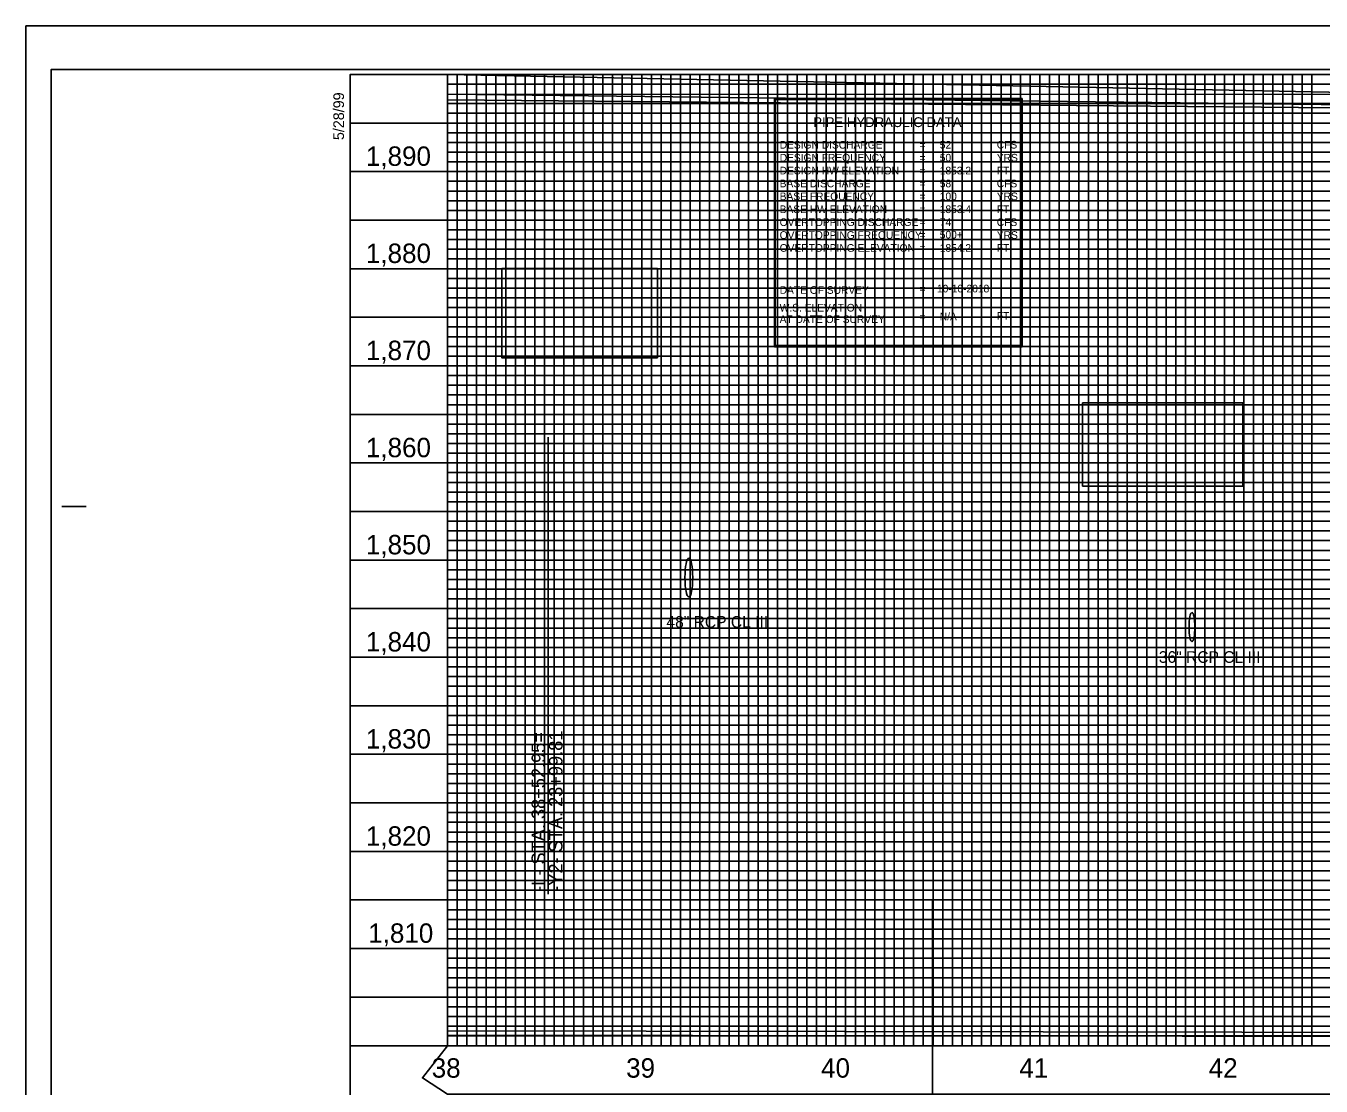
# Model space of a CAD drawing. Extents: x 557032 to 562069, y 513430 to 515874.
# Drawn here: x 557032 to 557699, y 515328 to 515874 of the extents above; entities that cross this region are included whole.
import ezdxf

# ---------------------------------------------------------------- set-up
doc = ezdxf.new("R2010")
doc.units = 0
for name, color, linetype in [('Default', 7, 'Continuous'), ('Exist Profile Cell', 7, 'Continuous'), ('Exist Vertical Profile Horizontal Axis Label Major', 7, 'Continuous'), ('Exist Vertical Profile Vertical Axis Label', 7, 'Continuous'), ('Prop Vertical Profile Curve Label', 7, 'Continuous'), ('Prop VPI Label', 7, 'Continuous'), ('Scratch_Level_1', 7, 'Continuous'), ('Scratch_Level_5', 7, 'Continuous'), ('Sheet Cutting Line CELL', 7, 'Continuous'), ('Sheet DOT Grid CELL', 7, 'Continuous'), ('Sheet Layout Profile Border Port 1', 7, 'Continuous'), ('Sheet Plot Border Inside CELL', 7, 'Continuous'), ('Sheet Plot Border Outside CELL', 7, 'Continuous'), ('Sheet Profile CELL', 7, 'Continuous'), ('Sheet Profile Grid Major CELL', 7, 'Continuous'), ('Sheet Profile Grid Middle CELL', 7, 'Continuous'), ('Sheet Profile Grid Minor CELL', 7, 'Continuous')]:
    doc.layers.add(name, color=color, linetype=linetype)

msp = doc.modelspace()

# ---------------------------------------------------------------- linework, layer by layer
at = {"layer": 'Default'}
for centre, major_axis in [((557373.73, 515590.31), (0, 10)), ((557632.73, 515564.81), (0, 7.5))]:
    msp.add_ellipse(centre, major_axis=major_axis, ratio=0.2, dxfattribs=at)
at = {"layer": 'Exist Profile Cell'}
msp.add_line((557499.18, 515173.85), (557499.18, 515423.85), dxfattribs=at)
at = {"layer": 'Prop Vertical Profile Curve Label'}
for points in [[(557417.87, 515836.9), (557545.27, 515836.9), (557545.27, 515709.09), (557417.87, 515709.09)], [(557277.44, 515749.39), (557357.56, 515749.39), (557357.56, 515703.4), (557277.44, 515703.4)], [(557576.47, 515680.15), (557658.85, 515680.15), (557658.85, 515637.38), (557576.47, 515637.38)]]:
    msp.add_lwpolyline(points, close=True, dxfattribs=at)
at = {"layer": 'Prop VPI Label'}
msp.add_line((557301.28, 515662.58), (557301.28, 515427.35), dxfattribs=at)
msp.add_lwpolyline([(557418.13, 515709.83), (557544.69, 515709.83), (557544.69, 515836.39), (557418.13, 515836.39)], close=True, dxfattribs=at)
at = {"layer": 'Scratch_Level_1'}
for p in [(557649.45, 515354.16), (557649.45, 515354.16), (557649.45, 515353.5)]:
    msp.add_line(p, (557649.45, 515680.98), dxfattribs=at)
at = {"layer": 'Scratch_Level_5'}
for p, q in [((557249.42, 515839.17), (557249.42, 515356.85)), ((557249.45, 515836.19), (557249.45, 515354.68))]:
    msp.add_line(p, q, dxfattribs=at)
msp.add_lwpolyline([(558499.4, 515824.23), (557249.45, 515849.28), (557249.45, 515349.28), (557236.61, 515332.67), (557249.45, 515324.28), (558649.45, 515324.28), (558662.72, 515334.01), (558649.45, 515349.28), (558649.45, 515688.23), (558499.4, 515688.23)], close=True, dxfattribs=at)
for points in [[(558649.42, 515686.42), (558641.97, 515686.42), (558497.02, 515687.96), (558497.02, 515823.15), (558090.9, 515829.21), (557249.42, 515839.17)], [(558649.45, 515682.57), (558492.81, 515683.83), (558490.11, 515820.17), (558049.46, 515829.04), (557249.45, 515836.19)], [(557249.42, 515356.85), (558373.93, 515355.08), (558412.39, 515354.77), (558649.42, 515355.8)], [(557249.45, 515354.68), (558384.27, 515353.2), (558399.94, 515350.88), (558440.57, 515354.03), (558649.45, 515354.48)]]:
    msp.add_lwpolyline(points, dxfattribs=at)
at = {"layer": 'Sheet Cutting Line CELL'}
for p, q in [((558716.45, 515874.28), (557032.45, 515874.28)), ((557032.45, 515874.28), (557032.45, 514774.28))]:
    msp.add_line(p, q, dxfattribs=at)
at = {"layer": 'Sheet DOT Grid CELL'}
for p, q in [((557249.45, 515349.28), (557249.45, 515849.28)), ((557299.45, 515349.28), (557299.45, 515849.28)), ((557349.45, 515349.28), (557349.45, 515849.28)), ((557399.45, 515349.28), (557399.45, 515849.28)), ((557449.45, 515349.28), (557449.45, 515849.28)), ((557499.45, 515349.28), (557499.45, 515849.28)), ((557549.45, 515349.28), (557549.45, 515849.28)), ((557599.45, 515349.28), (557599.45, 515849.28)), ((557649.45, 515349.28), (557649.45, 515849.28)), ((558499.4, 515799.28), (557199.45, 515799.28)), ((558499.4, 515749.28), (557199.45, 515749.28)), ((558499.45, 515699.28), (557199.45, 515699.28)), ((558699.45, 515649.28), (557199.45, 515649.28)), ((558699.45, 515599.28), (557199.45, 515599.28)), ((558699.45, 515549.28), (557199.45, 515549.28)), ((558699.45, 515499.28), (557199.45, 515499.28)), ((558699.45, 515449.28), (557199.45, 515449.28)), ((558699.45, 515399.28), (557199.45, 515399.28))]:
    msp.add_line(p, q, dxfattribs=at)
at = {"layer": 'Sheet Layout Profile Border Port 1'}
for points in [[(557249.45, 515688.23), (557249.45, 515349.28), (558649.45, 515349.28), (558649.45, 515688.23)], [(557249.45, 515688.23), (557249.45, 515354.68)], [(557249.45, 515688.23), (557249.45, 515354.13)]]:
    msp.add_lwpolyline(points, dxfattribs=at)
at = {"layer": 'Sheet Plot Border Inside CELL'}
msp.add_lwpolyline([(557045.45, 514796.73), (558711.95, 514796.73), (558711.95, 515851.83), (557045.45, 515851.83)], close=True, dxfattribs=at)
at = {"layer": 'Sheet Plot Border Outside CELL'}
msp.add_lwpolyline([(557032.45, 514774.28), (558716.45, 514774.28), (558716.45, 515874.28), (557032.45, 515874.28)], close=True, dxfattribs=at)
at = {"layer": 'Sheet Profile CELL'}
for p, q in [((557050.95, 515626.78), (557063.45, 515626.78)), ((557199.45, 515349.28), (558699.45, 515349.28))]:
    msp.add_line(p, q, dxfattribs=at)
msp.add_lwpolyline([(558699.45, 515849.28), (557199.45, 515849.28), (557199.45, 514799.28), (558699.45, 514799.28)], close=True, dxfattribs=at)
at = {"layer": 'Sheet Profile Grid Major CELL'}
for points in [[(557249.45, 515849.28), (557249.45, 515349.28), (557299.45, 515349.28), (557299.45, 515849.28), (557349.45, 515849.28), (557349.45, 515349.28), (557399.45, 515349.28), (557399.45, 515849.28), (557449.45, 515849.28), (557449.45, 515349.28), (557499.45, 515349.28), (557499.45, 515849.28), (557549.45, 515849.28), (557549.45, 515349.28), (557599.45, 515349.28), (557599.45, 515849.28), (557649.45, 515849.28), (557649.45, 515349.28), (557699.45, 515349.28)], [(557199.45, 515799.28), (558499.45, 515799.28)], [(558499.45, 515749.28), (557199.45, 515749.28), (557199.45, 515699.28), (558499.45, 515699.28)], [(558699.45, 515649.28), (557199.45, 515649.28), (557199.45, 515599.28), (558699.45, 515599.28)], [(558699.45, 515549.28), (557199.45, 515549.28), (557199.45, 515499.28), (558699.45, 515499.28)], [(558699.45, 515449.28), (557199.45, 515449.28), (557199.45, 515449.28), (557199.45, 515399.28), (558699.45, 515399.28)]]:
    msp.add_lwpolyline(points, dxfattribs=at)
at = {"layer": 'Sheet Profile Grid Middle CELL'}
msp.add_line((557199.45, 515824.28), (558499.4, 515824.28), dxfattribs=at)
for points in [[(557274.45, 515849.28), (557274.45, 515349.28), (557324.45, 515349.28), (557324.45, 515849.28), (557374.45, 515849.28), (557374.45, 515349.28), (557424.45, 515349.28), (557424.45, 515849.28), (557474.45, 515849.28), (557474.45, 515349.28), (557524.45, 515349.28), (557524.45, 515849.28), (557574.45, 515849.28), (557574.45, 515349.28), (557624.45, 515349.28), (557624.45, 515849.28), (557674.45, 515849.28), (557674.45, 515349.28), (557724.45, 515349.28)], [(558499.45, 515774.28), (557199.45, 515774.28), (557199.45, 515724.28), (558499.45, 515724.28)], [(558699.45, 515674.28), (557199.45, 515674.28), (557199.45, 515624.28), (558524.45, 515624.28)], [(558699.45, 515574.28), (557199.45, 515574.28), (557199.45, 515524.28), (558699.45, 515524.28)], [(558699.45, 515474.28), (557199.45, 515474.28), (557199.45, 515424.28), (558699.45, 515424.28)], [(558699.45, 515374.28), (557199.45, 515374.28)]]:
    msp.add_lwpolyline(points, dxfattribs=at)
at = {"layer": 'Sheet Profile Grid Minor CELL'}
for p, q in [((557249.45, 515844.28), (558499.45, 515844.28)), ((557249.45, 515839.28), (557249.45, 515839.28)), ((558499.45, 515839.28), (557249.45, 515838.93)), ((557249.45, 515834.28), (558499.45, 515834.28)), ((558499.4, 515714.28), (557249.45, 515714.28)), ((558499.45, 515709.28), (557249.45, 515709.28)), ((558499.45, 515704.28), (557249.45, 515704.28)), ((557249.45, 515694.28), (558499.45, 515694.28)), ((558499.45, 515689.28), (557249.45, 515689.28)), ((557249.45, 515684.28), (558649.45, 515684.28)), ((558649.45, 515664.28), (557249.45, 515664.28)), ((557249.45, 515659.28), (558649.45, 515659.28)), ((558649.45, 515639.28), (557249.45, 515639.28)), ((557249.45, 515634.28), (558649.45, 515634.28)), ((558649.45, 515614.28), (557249.45, 515614.28)), ((557249.45, 515609.28), (558649.45, 515609.28)), ((558649.45, 515604.28), (557249.45, 515604.28)), ((557249.45, 515594.28), (558649.45, 515594.28)), ((558649.45, 515589.28), (557249.45, 515589.28)), ((557249.45, 515584.28), (558649.45, 515584.28)), ((558649.45, 515579.28), (557249.45, 515579.28)), ((557249.45, 515569.28), (558649.45, 515569.28)), ((558649.45, 515564.28), (557249.45, 515564.28)), ((557249.45, 515559.28), (558649.45, 515559.28)), ((558649.45, 515554.28), (557249.45, 515554.28)), ((557249.45, 515544.28), (558649.45, 515544.28)), ((558649.45, 515539.28), (557249.45, 515539.28)), ((557249.45, 515534.28), (558649.45, 515534.28)), ((558649.45, 515529.28), (557249.45, 515529.28)), ((557249.45, 515519.28), (558649.45, 515519.28)), ((558649.45, 515514.28), (557249.45, 515514.28)), ((557249.45, 515509.28), (558649.45, 515509.28)), ((558649.45, 515504.28), (557249.45, 515504.28)), ((557249.45, 515494.28), (558649.45, 515494.28)), ((558649.45, 515489.28), (557249.45, 515489.28)), ((557249.45, 515484.28), (558649.45, 515484.28)), ((558649.45, 515479.28), (557249.45, 515479.28)), ((557249.45, 515469.28), (558649.45, 515469.28)), ((558649.45, 515464.28), (557249.45, 515464.28)), ((558649.45, 515459.28), (557249.45, 515459.28)), ((558649.45, 515454.28), (557249.45, 515454.28)), ((557249.45, 515444.28), (558649.45, 515444.28)), ((558649.45, 515439.28), (557249.45, 515439.28)), ((557249.45, 515434.28), (558649.45, 515434.28)), ((558649.45, 515429.28), (557249.45, 515429.28)), ((557249.45, 515419.28), (558649.45, 515419.28)), ((558649.45, 515414.28), (557249.45, 515414.28)), ((557249.45, 515409.28), (558649.45, 515409.28)), ((558649.45, 515404.28), (557249.45, 515404.28)), ((557249.45, 515394.28), (558649.45, 515394.28)), ((558649.45, 515389.28), (557249.45, 515389.28)), ((557249.45, 515384.28), (558649.45, 515384.28)), ((558649.45, 515379.28), (557249.45, 515379.28)), ((557249.45, 515369.28), (558649.45, 515369.28)), ((558649.45, 515364.28), (557249.45, 515364.28)), ((557249.45, 515359.28), (558649.45, 515359.28))]:
    msp.add_line(p, q, dxfattribs=at)
for points in [[(557254.45, 515849.28), (557254.45, 515349.28), (557259.45, 515349.28), (557259.45, 515849.28), (557264.45, 515849.28), (557264.45, 515349.28), (557269.45, 515349.28), (557269.45, 515849.28), (557279.45, 515849.28), (557279.45, 515349.28), (557284.45, 515349.28), (557284.45, 515849.28), (557289.45, 515849.28), (557289.45, 515349.28), (557294.45, 515349.28), (557304.45, 515349.28), (557309.45, 515349.28), (557309.45, 515849.28), (557314.45, 515849.28), (557314.45, 515349.28), (557319.45, 515349.28), (557319.45, 515849.28), (557329.45, 515849.28), (557329.45, 515349.28), (557334.45, 515349.28), (557334.45, 515849.28), (557339.45, 515849.28), (557339.45, 515349.28), (557344.45, 515349.28), (557344.45, 515849.28), (557354.45, 515849.28), (557354.45, 515349.28), (557359.45, 515349.28), (557359.45, 515849.28), (557364.45, 515849.28), (557364.45, 515349.28), (557369.45, 515349.28), (557369.45, 515849.28), (557379.45, 515849.28), (557379.45, 515349.28), (557384.45, 515349.28), (557384.45, 515849.28), (557389.45, 515849.28), (557389.45, 515349.28), (557394.45, 515349.28), (557394.45, 515849.28), (557404.45, 515849.28), (557404.45, 515349.28), (557409.45, 515349.28), (557409.45, 515849.28), (557414.45, 515849.28), (557414.45, 515349.28), (557419.45, 515349.28), (557419.45, 515849.28), (557429.45, 515849.28), (557429.45, 515349.28), (557434.45, 515349.28), (557434.45, 515849.28), (557439.45, 515849.28), (557439.45, 515349.28), (557444.45, 515349.28), (557444.45, 515849.28), (557454.45, 515849.28), (557454.45, 515349.28), (557459.45, 515349.28), (557459.45, 515849.28), (557464.45, 515849.28), (557464.45, 515349.28)], [(557294.45, 515349.28), (557294.45, 515849.28), (557304.45, 515849.28), (557304.45, 515349.28)], [(557464.45, 515349.28), (557469.45, 515349.28), (557469.45, 515849.28), (557479.45, 515849.28), (557479.45, 515349.28), (557484.45, 515349.28), (557484.45, 515849.28), (557489.45, 515849.28), (557489.45, 515349.28), (557494.45, 515349.28), (557494.45, 515849.28), (557504.45, 515849.28), (557504.45, 515349.28), (557509.45, 515349.28), (557509.45, 515849.28), (557514.45, 515849.28), (557514.45, 515349.28), (557519.45, 515349.28), (557519.45, 515849.28), (557529.45, 515849.28), (557529.45, 515349.28), (557534.45, 515349.28), (557534.45, 515849.28), (557539.45, 515849.28), (557539.45, 515349.28), (557544.45, 515349.28), (557544.45, 515849.28), (557554.45, 515849.28), (557554.45, 515349.28), (557559.45, 515349.28), (557559.45, 515849.28), (557564.45, 515849.28), (557564.45, 515349.28), (557569.45, 515349.28), (557569.45, 515849.28), (557579.45, 515849.28), (557579.45, 515349.28), (557584.45, 515349.28), (557584.45, 515849.28), (557589.45, 515849.28), (557589.45, 515349.28), (557594.45, 515349.28), (557594.45, 515849.28), (557604.45, 515849.28), (557604.45, 515349.28), (557609.45, 515349.28), (557609.45, 515849.28), (557614.45, 515849.28), (557614.45, 515349.28), (557619.45, 515349.28), (557619.45, 515849.28), (557629.45, 515849.28), (557629.45, 515349.28), (557634.45, 515349.28), (557634.45, 515849.28), (557639.45, 515849.28), (557639.45, 515349.28), (557644.45, 515349.28), (557644.45, 515849.28), (557654.45, 515849.28), (557654.45, 515349.28), (557659.45, 515349.28), (557659.45, 515849.28), (557664.45, 515849.28), (557664.45, 515349.28), (557669.45, 515349.28), (557669.45, 515849.28), (557679.45, 515849.28), (557679.45, 515349.28), (557684.45, 515349.28), (557684.45, 515849.28), (557689.45, 515849.28), (557689.45, 515349.28), (557694.45, 515349.28), (557694.45, 515849.28), (557704.45, 515849.28)], [(558499.45, 515829.28), (557249.45, 515829.28), (557249.45, 515819.28), (558499.45, 515819.28)], [(558499.4, 515814.28), (557249.45, 515814.28), (557249.45, 515809.28), (558499.45, 515809.28)], [(558499.45, 515804.28), (557249.45, 515804.28), (557249.45, 515794.28), (558499.45, 515794.28)], [(558499.45, 515789.28), (557249.45, 515789.28), (557249.45, 515784.28), (558499.45, 515784.28)], [(558499.45, 515779.28), (557249.45, 515779.28), (557249.45, 515769.28), (558499.45, 515769.28)], [(558499.45, 515764.28), (557249.45, 515764.28), (557249.45, 515759.28), (558499.45, 515759.28)], [(558499.45, 515754.28), (557249.45, 515754.28), (557249.45, 515744.28), (558499.45, 515744.28)], [(558499.45, 515739.18), (557249.55, 515739.18), (557249.55, 515734.28), (558499.45, 515734.28)], [(558499.45, 515729.28), (557249.45, 515729.28), (557249.45, 515719.28), (558499.45, 515719.28)], [(558649.45, 515679.28), (557249.45, 515679.28), (557249.45, 515669.28), (558649.45, 515669.28)], [(558649.45, 515654.28), (557249.45, 515654.28), (557249.45, 515644.28), (558649.45, 515644.28)], [(558649.45, 515629.28), (557249.45, 515629.28), (557249.45, 515619.28), (558649.45, 515619.28)], [(558649.45, 515354.28), (557249.45, 515354.28)]]:
    msp.add_lwpolyline(points, dxfattribs=at)

# ---------------------------------------------------------------- texts
at = {"layer": 'Default'}
for s, p in [('48" RCP CL III', (557362.21, 515564.46)), ('36" RCP CL III', (557615.69, 515546.37))]:
    msp.add_text(s, height=6, dxfattribs=at).set_placement(p)
at = {"layer": 'Exist Vertical Profile Horizontal Axis Label Major'}
for s, p in [('38', (557241.38, 515332.81)), ('39', (557341.46, 515332.81)), ('40', (557441.82, 515332.81)), ('41', (557543.88, 515332.81)), ('42', (557641.38, 515332.81))]:
    msp.add_text(s, height=10, dxfattribs=at).set_placement(p)
at = {"layer": 'Exist Vertical Profile Vertical Axis Label'}
for s, p in [('1,890', (557207.5, 515802.23)), ('1,890', (557207.5, 515802.23)), ('1,890', (557207.5, 515802.23)), ('1,890', (557207.5, 515802.23)), ('1,880', (557207.5, 515752.23)), ('1,880', (557207.5, 515752.23)), ('1,880', (557207.5, 515752.23)), ('1,880', (557207.5, 515752.23)), ('1,870', (557207.5, 515702.23)), ('1,870', (557207.5, 515702.23)), ('1,870', (557207.5, 515702.23)), ('1,870', (557207.5, 515702.23)), ('1,860', (557207.5, 515652.23)), ('1,860', (557207.5, 515652.23)), ('1,860', (557207.5, 515652.23)), ('1,860', (557207.5, 515652.23)), ('1,850', (557207.5, 515602.23)), ('1,850', (557207.5, 515602.23)), ('1,850', (557207.5, 515602.23)), ('1,850', (557207.5, 515602.23)), ('1,840', (557207.5, 515552.23)), ('1,840', (557207.5, 515552.23)), ('1,840', (557207.5, 515552.23)), ('1,840', (557207.5, 515552.23)), ('1,830', (557207.5, 515502.23)), ('1,830', (557207.5, 515502.23)), ('1,830', (557207.5, 515502.23)), ('1,830', (557207.5, 515502.23)), ('1,820', (557207.5, 515452.23)), ('1,820', (557207.5, 515452.23)), ('1,820', (557207.5, 515452.23)), ('1,820', (557207.5, 515452.23)), ('1,810', (557208.7, 515402.23)), ('1,810', (557208.7, 515402.23)), ('1,810', (557208.7, 515402.23)), ('1,810', (557208.7, 515402.23))]:
    msp.add_text(s, height=10, dxfattribs=at).set_placement(p)
at = {"layer": 'Prop VPI Label'}
for s, height, p in [('PIPE HYDRAULIC DATA', 5.0625, (557437.76, 515822.19)), ('DESIGN DISCHARGE', 3.9375, (557420.49, 515811.11)), ('=     52', 3.937, (557492.53, 515811.11)), ('CFS', 3.937, (557532.27, 515811.16)), ('DESIGN FREQUENCY', 3.9375, (557420.49, 515804.47)), ('=     50', 3.937, (557492.53, 515804.47)), ('YRS', 3.937, (557532.27, 515804.47)), ('DESIGN HW ELEVATION', 3.9375, (557420.49, 515797.83)), ('=     1853.2', 3.9375, (557492.53, 515797.83)), ('FT', 3.937, (557532.27, 515797.83)), ('BASE DISCHARGE', 3.9375, (557420.49, 515791.19)), ('=     58', 3.937, (557492.53, 515791.19)), ('CFS', 3.937, (557532.27, 515791.19)), ('BASE FREQUENCY', 3.9375, (557420.49, 515784.56)), ('=     100', 3.937, (557492.53, 515784.56)), ('YRS', 3.937, (557532.27, 515784.56)), ('BASE HW ELEVATION', 3.9375, (557420.49, 515777.92)), ('=     1853.4', 3.9375, (557492.53, 515777.92)), ('FT', 3.937, (557532.27, 515777.92)), ('OVERTOPPING DISCHARGE', 3.9375, (557420.49, 515771.28)), ('=     74', 3.937, (557492.53, 515771.28)), ('CFS', 3.937, (557532.27, 515771.28)), ('OVERTOPPING FREQUENCY', 3.9375, (557420.49, 515764.64)), ('=     500+', 3.937, (557492.53, 515764.81)), ('YRS', 3.937, (557532.27, 515764.64)), ('OVERTOPPING ELEVATION', 3.9375, (557420.49, 515758.01)), ('=     1854.2', 3.9374, (557492.53, 515758.01)), ('FT', 3.937, (557532.27, 515758.01)), ('DATE OF SURVEY', 3.9375, (557420.49, 515736.35)), ('=    10-10-2018', 3.9375, (557492.53, 515737.08)), ('W.S. ELEVATION', 3.9375, (557420.49, 515727.24)), ('AT DATE OF SURVEY', 3.9375, (557420.49, 515721.33)), ('=     N/A', 3.937, (557492.53, 515722.71)), ('FT', 3.937, (557532.27, 515723.05))]:
    msp.add_text(s, height=height, dxfattribs=at).set_placement(p)
for s, p in [('-L- STA. 38+52.95=', (557299.8, 515428.51)), ('-Y2- STA. 23+99.81', (557308.68, 515428.51))]:
    msp.add_text(s, height=7, rotation=90, dxfattribs=at).set_placement(p)
at = {"layer": 'Sheet Profile CELL'}
msp.add_text('5/28/99', height=5.5, rotation=90, dxfattribs=at).set_placement((557196.22, 515815.5))

doc.saveas('drawing.dxf')
